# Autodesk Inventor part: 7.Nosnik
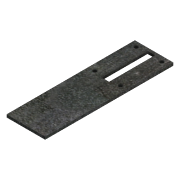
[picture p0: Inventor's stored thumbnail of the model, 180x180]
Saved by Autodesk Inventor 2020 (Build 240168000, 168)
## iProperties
Created: 2022-03
Part Number: 7.Nosnik
Material: Steel
Document SubType Name: Modeling
Designer: marti
Density: 7.85 g/cm^3
Appearance: Plate
Author: marti
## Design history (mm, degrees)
sketch "Sketch1"
  geometry: L1 (15, 50)-(-15, 50); L2 (-15, 50)-(-15, -50); L3 (-15, -50)-(15, -50); L4 (15, -50)-(15, 50); L5 (15, 50)-(-15, -50); L6 (-15, 50)-(15, -50); 1 further point
  constraints: 12 end point, 2 midpoint, 2 parallel, 1 horizontal, 1 perpendicular
  dimensions: "d0" = 30 distance of L3.end L2.end; "d1" = 100 distance of L2.end L1.end
extrude "Extrusion1" new body sketch "Sketch1" distance "d2" = 2; taper "d3" = 0 deg
sketch "Sketch2"
  geometry: L1 (15, 50)-(-15, 50) reference; L2 (0, 50)-(0, 47.9); L3 (0, 47.9)-(-3, 47.9); L4 (-3, 47.9)-(3, 47.9); L5 (3, 47.9)-(3, 11.9); L6 (3, 11.9)-(-3, 11.9); L7 (-3, 11.9)-(-3, 47.9); 2 further points
  constraints: 12 end point, 2 parallel, 2 perpendicular, 1 horizontal, 1 midpoint, 1 vertical
  dimensions: "d4" = 2.1 distance of L2.start L2.end; "d5" = 3 distance of L2.end L3.end; "d6" = 6 distance of L5.end L6.end; "d7" = 36 distance of L4.end L5.end
extrude "Extrusion2" cut sketch "Sketch2" distance "d8" = 2; taper "d9" = 0 deg
sketch "Sketch3"
  geometry: L1 (15, -50)-(15, 50) reference; L2 (15, 50)-(-15, 50) reference; C1 r 1.5 at (10, 46); 1 further point
  constraints: 1 centre point
  dimensions: "d10" = 3 diameter of C1; "d11" = 5 distance from line of L1 C1.centre; "d12" = 4 distance from line of C1.centre L2
extrude "Extrusion3" cut sketch "Sketch3" distance "d13" = 2; taper "d14" = 0 deg
pattern_linear "Rectangular Pattern1" dims "d17" = 20
pattern_linear "Rectangular Pattern2" dims "d20" = 32.2
body "Solid1"
